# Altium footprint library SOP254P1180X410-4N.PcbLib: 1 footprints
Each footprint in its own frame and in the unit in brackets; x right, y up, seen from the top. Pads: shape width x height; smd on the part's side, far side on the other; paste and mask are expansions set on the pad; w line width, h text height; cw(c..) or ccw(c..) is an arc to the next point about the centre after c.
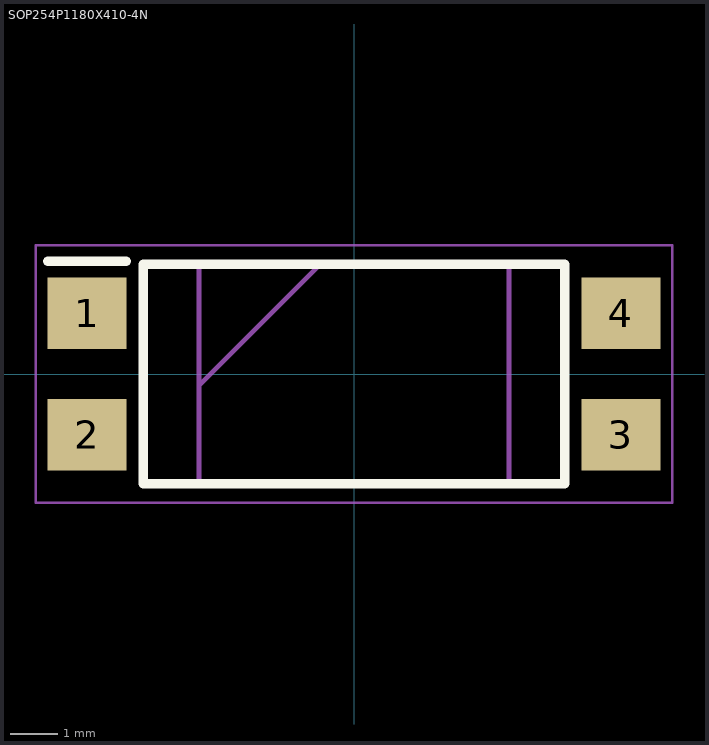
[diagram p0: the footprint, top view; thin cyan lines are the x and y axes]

## SOP254P1180X410-4N [mm]
pads (4):
  rect 1.65x1.5 smd: 1(-5.6,1.27) 2(-5.6,-1.27) 3(5.6,-1.27) 4(5.6,1.27)
Top Overlay:
  lines w0.2: -6.425,2.37 -4.775,2.37 ; -4.425,-2.3 4.425,-2.3 4.425,2.3 -4.425,2.3 -4.425,-2.3
Mechanical 15:
  lines w0.1: -3.25,-0.24 -0.71,2.3 ; -3.25,-2.3 3.25,-2.3 3.25,2.3 -3.25,2.3 -3.25,-2.3
Mechanical 20:
  lines w0.05: -6.675,-2.7 6.675,-2.7 6.675,2.7 -6.675,2.7 -6.675,-2.7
